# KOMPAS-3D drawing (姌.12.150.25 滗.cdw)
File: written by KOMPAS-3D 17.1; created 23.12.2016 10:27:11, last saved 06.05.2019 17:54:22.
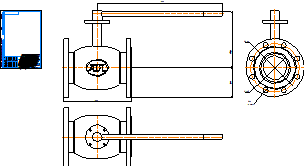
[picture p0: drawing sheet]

Sheet 1: A4, portrait

Title block, sheet 1: name: КШ.12.150.25 фф; material: Внимание! Данный продукт является объектом авторского права ООО «Торговый Дом АДЛ». / Запрещается изменение, копирование, распространение / (в том числе путем копирования на другие сайты и ресурсы в Интернете) / или любое иное использование информации и объектов без предварительного / согласия правообладателя (ООО «Торговый Дом АДЛ»).; sheets: 1; organisation: ООО "Торговый дом АДЛ"; sheet format: A4; stored path: C:\Users\tra\Desktop\2д чертежи\Шаровые краны БИВАЛ\КШ_Бивал_серия_11_12\KOMPAS_2D\КШ.12.150.25 фф.cdw

Views: Вид 1, Проекционный вид 2, Проекционный вид 3
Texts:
  Klimkovich
  ADL
Dimensions and other numbers on the sheet: 350; 645; 291,6; 150; 250; 149; 26; 8 Отв.; 1:1; 1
